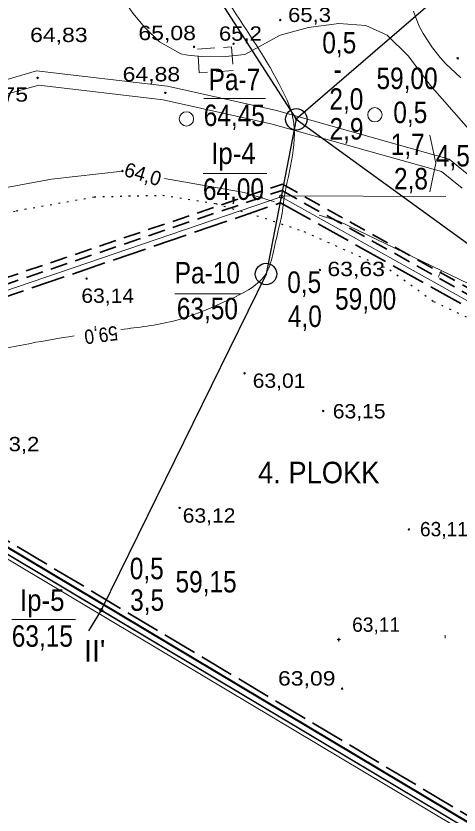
# Model space of a CAD drawing. Extents: x 628176 to 629009, y 6439913 to 6440496.
# Drawn here: x 628361.2 to 628423, y 6440112.2 to 6440223.6 of the extents above; entities that cross this region are included whole.
import ezdxf
from ezdxf.enums import TextEntityAlignment as Align

# ---------------------------------------------------------------- set-up
doc = ezdxf.new("R2010")
doc.units = 0
doc.header["$LTSCALE"] = 0.8
for name, pattern in [('DOTTED', [1.5, 0.3, -1.2]), ('LONG_DASHED', [7.5, 6, -1.5]), ('MEDIUM_DASHED', [4.5, 3, -1.5])]:
    doc.linetypes.add(name, pattern=pattern)
for name, color, linetype, lineweight in [('1', 7, 'Continuous', 13), ('11', 7, 'Continuous', 13), ('12', 7, 'Continuous', 13), ('14', 7, 'Continuous', 25), ('16', 7, 'Continuous', 13), ('21', 7, 'MEDIUM_DASHED', 35), ('3', 7, 'Continuous', 13), ('6', 7, 'Continuous', 13)]:
    doc.layers.add(name, color=color, linetype=linetype, lineweight=lineweight)

msp = doc.modelspace()

# ---------------------------------------------------------------- hatches: boundary and pattern name
at = {"layer": '1'}
for points in [[(628398.1428, 6440223.0639, 1), (628397.9428, 6440223.0639, 1)], [(628391.6314, 6440219.7575, 1), (628391.4314, 6440219.7575, 1)], [(628386.1184, 6440219.3249, 1), (628385.9184, 6440219.3249, 1)], [(628422.9132, 6440217.7205, 1), (628422.7132, 6440217.7205, 1)], [(628364.2749, 6440214.9768, 1), (628364.0749, 6440214.9768, 1)], [(628382.0995, 6440212.9031, 1), (628381.8995, 6440212.9031, 1)], [(628400.3907, 6440209.2196, 1), (628400.1907, 6440209.2196, 1)], [(628376.0999, 6440201.9999, 1), (628375.8999, 6440201.9999, 1)], [(628421.1991, 6440202.7925, 1), (628420.9991, 6440202.7925, 1)], [(628403.6745, 6440188.2069, 1), (628403.4745, 6440188.2069, 1)], [(628371.0999, 6440186.9999, 1), (628370.8999, 6440186.9999, 1)], [(628393.1669, 6440173.7815, 1), (628392.9669, 6440173.7815, 1)], [(628404.142, 6440168.5223, 1), (628403.942, 6440168.5223, 1)], [(628384.0999, 6440154.9999, 1), (628383.8999, 6440154.9999, 1)], [(628416.0999, 6440151.9999, 1), (628415.8999, 6440151.9999, 1)], [(628406.322, 6440136.628, 1), (628406.122, 6440136.628, 1)], [(628406.7767, 6440129.7825, 1), (628406.5767, 6440129.7825, 1)]]:
    msp.add_hatch(color=256, dxfattribs=at).paths.add_polyline_path(points)

# ---------------------------------------------------------------- linework, layer by layer
for p, q in [((628364, 6440215.96), (628355.36, 6440213.47)), ((628382.29, 6440213.86), (628364, 6440215.96)), ((628364.35, 6440213.99), (628355.36, 6440211.47)), ((628381.71, 6440211.95), (628364.35, 6440213.99)), ((628397.52, 6440210.44), (628382.29, 6440213.86)), ((628396.93, 6440208.53), (628381.71, 6440211.95)), ((628421.64, 6440203.63), (628397.52, 6440210.44)), ((628420.56, 6440201.95), (628396.93, 6440208.53)), ((628424.88, 6440201), (628421.64, 6440203.63)), ((628423.46, 6440199.59), (628420.56, 6440201.95)), ((628406.22, 6440136.63), (628405.97, 6440136.63)), ((628406.22, 6440136.63), (628406.22, 6440136.88)), ((628406.22, 6440136.63), (628406.22, 6440136.38)), ((628406.22, 6440136.63), (628406.47, 6440136.63))]:
    msp.add_line(p, q, dxfattribs=at)
at = {"layer": '1', "linetype": 'MEDIUM_DASHED'}
msp.add_lwpolyline([(628386.51, 6440219), (628391.24, 6440219.32), (628391.47, 6440216.02), (628386.74, 6440215.69)], close=True, dxfattribs=at)
at = {"layer": '1', "linetype": 'DOTTED', "lineweight": 25}
msp.add_lwpolyline([(628352.66, 6440194.21), (628361.18, 6440196.45), (628372.08, 6440198.4), (628381.65, 6440198.63), (628389.03, 6440197.45), (628395.92, 6440195.41), (628401.35, 6440193.56), (628413.35, 6440188.21), (628419.46, 6440183.8), (628429.96, 6440178.83), (628439.17, 6440172.52), (628442.41, 6440166.94), (628444.75, 6440162.25), (628447.66, 6440156.67), (628451.45, 6440151.65), (628455.36, 6440146.51), (628457.42, 6440140.66), (628458.82, 6440136.02), (628463.06, 6440130.1), (628466.63, 6440124.3), (628470.09, 6440119.39), (628472.43, 6440114.37), (628474.33, 6440109.9)], dxfattribs=at)
at = {"layer": '1'}
for centre, radius in [((628398.0428, 6440223.0639), 0.1), ((628391.5314, 6440219.7575), 0.1), ((628386.0184, 6440219.3249), 0.1), ((628422.8132, 6440217.7205), 0.1), ((628364.1749, 6440214.9768), 0.1), ((628381.9995, 6440212.9031), 0.1), ((628384.9529, 6440209.2698), 1), ((628411.2547, 6440209.8412), 1), ((628400.2907, 6440209.2196), 0.1), ((628375.9999, 6440201.9999), 0.1), ((628421.0991, 6440202.7925), 0.1), ((628403.5745, 6440188.2069), 0.1), ((628370.9999, 6440186.9999), 0.1), ((628393.0669, 6440173.7815), 0.1), ((628404.042, 6440168.5223), 0.1), ((628383.9999, 6440154.9999), 0.1), ((628415.9999, 6440151.9999), 0.1), ((628406.222, 6440136.628), 0.1), ((628406.6767, 6440129.7825), 0.1)]:
    msp.add_circle(centre, radius, dxfattribs=at)
at = {"layer": '11'}
for points in [[(628497.5, 6440118.54), (628474.19, 6440080.39), (628272.25, 6440200.89), (628236.02, 6440221.83), (628393.19, 6440398.39)], [(628320.67, 6440172), (628398.18, 6440198.42), (628472.21, 6440157.1), (628497.5, 6440118.54)]]:
    msp.add_lwpolyline(points, dxfattribs=at)
at = {"layer": '12'}
for p, q in [((628387.38, 6440212.1), (628396, 6440212.1)), ((628387.29, 6440201.67), (628396.19, 6440201.67)), ((628398.13, 6440198.54), (628421.16, 6440198.44)), ((628383.35, 6440184.88), (628392.51, 6440184.88)), ((628360.58, 6440139.43), (628369.45, 6440139.43))]:
    msp.add_line(p, q, dxfattribs=at)
msp.add_lwpolyline([(628418.95, 6440207), (628419.76, 6440203.08), (628418.95, 6440199.1)], dxfattribs=at)
at = {"layer": '12', "lineweight": 25}
for centre in [(628400.2907, 6440209.2196), (628396.0604, 6440187.6302)]:
    msp.add_circle(centre, 1.5, dxfattribs=at)
at = {"layer": '12'}
for centre in [(628398.1756, 6440198.4249), (628373.061, 6440140.7342)]:
    msp.add_circle(centre, 0.25, dxfattribs=at)
at = {"layer": '14'}
for p, q in [((628396.06, 6440187.63), (628373.06, 6440140.73)), ((628373.06, 6440140.73), (628371.26, 6440137.83))]:
    msp.add_line(p, q, dxfattribs=at)
for points in [[(628326.62, 6440323.6), (628400.29, 6440209.22), (628472.21, 6440157.1), (628497.5, 6440118.54), (628498.85, 6440116.47)], [(628485.59, 6440282.78), (628439.01, 6440242.62), (628400.29, 6440209.22)], [(628400.29, 6440209.22), (628398.18, 6440198.42), (628396.06, 6440187.63)], [(628267.86, 6440203.3), (628311.23, 6440177.63), (628327.53, 6440167.88), (628373.06, 6440140.73), (628474.19, 6440080.39), (628476.16, 6440079.17)]]:
    msp.add_lwpolyline(points, dxfattribs=at)
at = {"layer": '16'}
for points in [[(628370.47, 6440282.1), (628370.94, 6440277.37), (628372.06, 6440266.2), (628373.18, 6440254.09), (628375.41, 6440248.69), (628378.39, 6440243.47), (628386.22, 6440232.48), (628390.87, 6440225.4), (628398.32, 6440213.3), (628399.81, 6440209.39), (628399.63, 6440203.43), (628398.5, 6440197.6), (628398.32, 6440196.1)], [(628409.9, 6440254.58), (628412.29, 6440252.6), (628420.3, 6440245.33), (628427.75, 6440237.7), (628436.13, 6440222.98), (628444.52, 6440204.92), (628447.68, 6440184.24), (628451.78, 6440164.12), (628460.72, 6440143.45), (628472.64, 6440122.77), (628478.97, 6440106.2), (628480.84, 6440088.32)], [(628398.32, 6440196.1), (628397.09, 6440190.75), (628396.09, 6440187.75), (628391.14, 6440184.16), (628383.08, 6440181.07), (628375.77, 6440179.89)], [(628369.28, 6440179.01), (628363.18, 6440177.96), (628347.39, 6440174.51), (628332.71, 6440170.73), (628324.04, 6440166.29)], [(628421.05, 6440137.24), (628421.05, 6440136.93), (628421.05, 6440136.85)]]:
    msp.add_spline(points, degree=3, dxfattribs=at)
at = {"layer": '21'}
for points in [[(628321.66, 6440174.2), (628398.34, 6440200.16), (628470.2, 6440160.05)], [(628321.72, 6440173.24), (628398.26, 6440199.29), (628472.77, 6440157.71), (628496.99, 6440120.78)]]:
    msp.add_lwpolyline(points, dxfattribs=at)
at = {"layer": '21', "linetype": 'LONG_DASHED'}
for points in [[(628323.6, 6440172.11), (628398.09, 6440197.56), (628471.64, 6440156.5), (628496.07, 6440119.27)], [(628496.07, 6440119.27), (628473.65, 6440082.57), (628323.6, 6440172.11)]]:
    msp.add_lwpolyline(points, dxfattribs=at)
at = {"layer": '21', "linetype": 'Continuous', "lineweight": 40}
msp.add_lwpolyline([(628496.82, 6440118.96), (628473.92, 6440081.48), (628320.39, 6440173.09)], dxfattribs=at)
at = {"layer": '3'}
for p, q in [((628398.04, 6440220.93), (628393.12, 6440218.25)), ((628384.18, 6440218.37), (628385.13, 6440218.15)), ((628387, 6440217.97), (628385.13, 6440218.15)), ((628387, 6440217.97), (628390, 6440217.95)), ((628390, 6440217.95), (628393.12, 6440218.25)), ((628420.37, 6440217.83), (628421.11, 6440217)), ((628421.11, 6440217), (628423.25, 6440215)), ((628381.88, 6440200.96), (628393, 6440199)), ((628393, 6440199), (628397.23, 6440197.72)), ((628403.5, 6440195.82), (628406.22, 6440195)), ((628420.11, 6440187.2), (628420.55, 6440188.1))]:
    msp.add_line(p, q, dxfattribs=at)
for points in [[(628384.18, 6440218.37), (628381.18, 6440220), (628379.13, 6440222), (628377.48, 6440224), (628376.12, 6440226), (628375.42, 6440227), (628374.63, 6440228)], [(628416.67, 6440224.28), (628417, 6440223.3), (628417.45, 6440222.23), (628418, 6440221.18), (628419.31, 6440219.19), (628420.37, 6440217.83)], [(628398.04, 6440220.93), (628402, 6440222), (628406.22, 6440222.56), (628410, 6440222.28), (628412.96, 6440220.93), (628415.96, 6440218), (628418.98, 6440214), (628426, 6440206)], [(628356, 6440199), (628366.09, 6440200.87), (628376, 6440202)], [(628406.22, 6440195), (628427, 6440185), (628435, 6440179), (628441, 6440172), (628445.36, 6440164)]]:
    msp.add_lwpolyline(points, dxfattribs=at)
at = {"layer": '6'}
msp.add_lwpolyline([(628473.77, 6440079.94), (628271.95, 6440200.37), (628235.6, 6440221.38)], dxfattribs=at)

# ---------------------------------------------------------------- texts
at = {"layer": '1'}
for s, width, p in [('65,3', 1.15, (628399.14, 6440222.79)), ('65,08', 1.2, (628378.24, 6440220.26)), ('65,2', 1.15, (628389.49, 6440220.18)), ('64,83', 1.2, (628363.12, 6440219.99)), ('64,88', 1.2, (628376.04, 6440214.51)), ('64,75', 1.2, (628354.81, 6440211.68)), ('63,63', 1.2, (628404.63, 6440187.34)), ('63,14', 1.1, (628370.28, 6440183.61)), ('63,01', 1.1, (628394.2, 6440171.75)), ('63,15', 1.1, (628405.38, 6440167.49)), ('63,2', 1.15, (628358.42, 6440162.91)), ('63,12', 1.1, (628384.43, 6440152.94)), ('63,09', 1.2, (628397.73, 6440130.22))]:
    msp.add_text(s, height=2, dxfattribs=dict(at, width=width)).set_placement(p)
for p in [(628417.55, 6440151.04), (628408.08, 6440137.72)]:
    msp.add_text('63,11', height=2, dxfattribs=at).set_placement(p)
at = {"layer": '11', "width": 0.85}
for p in [(628406.285, 6440218.41), (628416.2, 6440208.68), (628401.39, 6440184.99), (628379.41, 6440145.05)]:
    msp.add_text('0,5', height=3, dxfattribs=at).set_placement(p, align=Align.CENTER)
at = {"layer": '12'}
for s, width, p in [('Pa-7', 0.85, (628391.64, 6440213.27)), ('-', 0.85, (628406.075, 6440214.7)), ('59,00', 0.85, (628415.75, 6440213.43)), ('2,0', 0.85, (628407.27, 6440210.54)), ('64,45', 0.85, (628391.63, 6440208.27)), ('2,9', 0.85, (628407.295, 6440206.39)), ('1,7', 0.85, (628415.84, 6440204.23)), ('Ip-4', 0.9, (628391.51, 6440202.97)), ('4,5', 0.85, (628422.145, 6440202.64)), ('2,8', 0.85, (628416.295, 6440199.43)), ('64,00', 0.85, (628391.51, 6440197.97)), ('Pa-10', 0.85, (628387.87, 6440186.31)), ('59,00', 0.85, (628409.965, 6440182.66)), ('63,50', 0.85, (628387.875, 6440181.31)), ('4,0', 0.85, (628401.48, 6440180.24)), ('59,15', 0.85, (628387.69, 6440143.21)), ('Ip-5', 0.9, (628364.82, 6440140.63)), ('3,5', 0.85, (628379.465, 6440140.64)), ('63,15', 0.85, (628364.83, 6440135.63))]:
    msp.add_text(s, height=3, dxfattribs=dict(at, width=width)).set_placement(p, align=Align.CENTER)
at = {"layer": '14'}
msp.add_text("II'", height=3, dxfattribs=at).set_placement((628372.135, 6440133.56), align=Align.CENTER)
at = {"layer": '16', "width": 0.9}
msp.add_text('59,0', height=2, rotation=187.6, dxfattribs=at).set_placement((628372.9072, 6440180.1008), align=Align.CENTER)
at = {"layer": '21', "width": 0.95}
msp.add_text('4. PLOKK', height=3, dxfattribs=at).set_placement((628403.42, 6440158.44), align=Align.CENTER)
at = {"layer": '3'}
msp.add_text('64,0', height=2, rotation=343.168, dxfattribs=at).set_placement((628376.09, 6440201.36))

doc.saveas('drawing.dxf')
